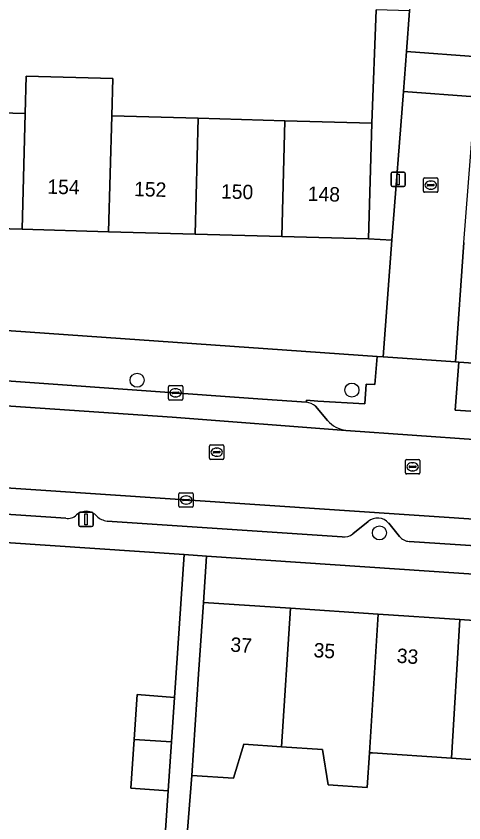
# Model space of a CAD drawing. Extents: x 159053 to 160042, y 380449 to 381423.
# Drawn here: x 159387.7 to 159418.7, y 381158.5 to 381214.5 of the extents above; entities that cross this region are included whole.
import ezdxf

# ---------------------------------------------------------------- set-up
doc = ezdxf.new("R2010")
doc.units = 0
for name, color, linetype in [('IMGEO_Berm_groen', 7, 'Continuous'), ('IMGEO_Boom', 7, 'Continuous'), ('IMGEO_Erf', 7, 'Continuous'), ('IMGEO_Kolk', 7, 'Continuous'), ('IMGEO_Lichtmast', 7, 'Continuous'), ('IMGEO_Pand', 7, 'Continuous'), ('IMGEO_Pand_nummerreeks', 7, 'Continuous'), ('IMGEO_Parkeervlak_open', 7, 'Continuous'), ('IMGEO_Rijbaan_lokaal_open', 7, 'Continuous'), ('IMGEO_Rioolput', 7, 'Continuous'), ('IMGEO_Voetpad_open', 7, 'Continuous')]:
    doc.layers.add(name, color=color, linetype=linetype)

msp = doc.modelspace()

# ---------------------------------------------------------------- linework, layer by layer
at = {"layer": 'IMGEO_Berm_groen'}
msp.add_lwpolyline([(159414.538, 381209.296), (159414.752, 381212.087), (159414.968, 381214.908), (159412.643, 381214.977), (159412.342, 381207.116), (159412.123, 381199.079), (159413.749, 381198.987)], close=True, dxfattribs=at)
at = {"layer": 'IMGEO_Boom'}
for centre in [(159396.061, 381189.257), (159410.962, 381188.573), (159412.878, 381178.655)]:
    msp.add_circle(centre, 0.489, dxfattribs=at)
at = {"layer": 'IMGEO_Erf'}
for points in [[(159352.243, 381208.754), (159358.251, 381208.591), (159364.259, 381208.427), (159370.267, 381208.263), (159376.275, 381208.099), (159382.281, 381207.936), (159388.289, 381207.772), (159388.359, 381210.379), (159394.368, 381210.218), (159394.298, 381207.608), (159400.305, 381207.444), (159406.313, 381207.28), (159412.342, 381207.116), (159412.643, 381214.977)], [(159337.817, 381196.156), (159412.725, 381190.897), (159413.137, 381190.868), (159413.749, 381198.987), (159412.123, 381199.079), (159406.098, 381199.243), (159400.09, 381199.407), (159394.083, 381199.571), (159388.074, 381199.735), (159382.067, 381199.899), (159376.06, 381200.063), (159370.052, 381200.227), (159364.044, 381200.391), (159358.036, 381200.555), (159352.028, 381200.719)], [(159418.746, 381198.827), (159418.155, 381190.521), (159418.399, 381190.504), (159489.16, 381185.654)], [(159465.572, 381146.862), (159463.56, 381159.946), (159457.638, 381160.343), (159451.96, 381160.723), (159446.274, 381161.104), (159440.588, 381161.485), (159434.913, 381161.865), (159429.234, 381162.245), (159423.569, 381162.624), (159417.883, 381163.005), (159412.393, 381163.373), (159412.184, 381163.387), (159412.031, 381160.979), (159409.33, 381161.165), (159408.933, 381163.61), (159406.07, 381163.806), (159403.458, 381163.985), (159402.742, 381161.616), (159399.854, 381161.814), (159399.452, 381156.561)]]:
    msp.add_lwpolyline(points, dxfattribs=at)
for points in [[(159395.856, 381164.312), (159396.06, 381167.421), (159398.657, 381167.233), (159399.325, 381177.147), (159374.158, 381178.842), (159370.465, 381164.045), (159365.639, 381161.495), (159363.677, 381133.592), (159398.457, 381131.162), (159398.959, 381143.89), (159397.15, 381152.623), (159396.964, 381150.031), (159393.385, 381150.287), (159393.57, 381152.879), (159388.745, 381153.224), (159388.848, 381154.667), (159395.186, 381154.243), (159395.426, 381157.83), (159398.017, 381157.657), (159398.223, 381160.746), (159395.633, 381160.919)], [(159400.883, 381177.042), (159400.666, 381173.825), (159406.716, 381173.419), (159412.792, 381173.011), (159418.457, 381172.631), (159424.13, 381172.25), (159429.823, 381171.867), (159435.525, 381171.485), (159441.199, 381171.104), (159446.901, 381170.721), (159452.564, 381170.341), (159458.247, 381169.959), (159464.177, 381169.561), (159464.393, 381172.763)]]:
    msp.add_lwpolyline(points, close=True, dxfattribs=at)
at = {"layer": 'IMGEO_Kolk'}
for p, q in [((159415.937, 381202.378), (159415.937, 381203.23)), ((159416.012, 381203.304), (159416.864, 381203.304)), ((159416.425, 381203.084), (159416.45, 381203.084)), ((159416.938, 381203.23), (159416.938, 381202.378)), ((159416.196, 381202.798), (159416.196, 381202.81)), ((159416.634, 381202.761), (159416.236, 381202.761)), ((159416.239, 381202.847), (159416.637, 381202.847)), ((159416.448, 381202.524), (159416.423, 381202.524)), ((159416.68, 381202.81), (159416.68, 381202.798)), ((159416.864, 381202.304), (159416.012, 381202.304)), ((159398.232, 381187.954), (159398.232, 381188.806)), ((159398.307, 381188.88), (159399.159, 381188.88)), ((159398.72, 381188.66), (159398.745, 381188.66)), ((159399.233, 381188.806), (159399.233, 381187.954)), ((159398.491, 381188.374), (159398.491, 381188.386)), ((159398.929, 381188.337), (159398.531, 381188.337)), ((159398.534, 381188.423), (159398.932, 381188.423)), ((159398.743, 381188.1), (159398.718, 381188.1)), ((159398.975, 381188.386), (159398.975, 381188.374)), ((159399.159, 381187.88), (159398.307, 381187.88)), ((159398.958, 381180.513), (159398.958, 381181.365)), ((159399.033, 381181.439), (159399.885, 381181.439)), ((159399.446, 381181.219), (159399.471, 381181.219)), ((159399.959, 381181.365), (159399.959, 381180.513)), ((159399.217, 381180.933), (159399.217, 381180.945)), ((159399.655, 381180.896), (159399.257, 381180.896)), ((159399.26, 381180.982), (159399.658, 381180.982)), ((159399.469, 381180.659), (159399.444, 381180.659)), ((159399.701, 381180.945), (159399.701, 381180.933)), ((159399.885, 381180.439), (159399.033, 381180.439))]:
    msp.add_line(p, q, dxfattribs=at)
for points in [[(159415.937, 381202.378), (159415.937, 381203.23)], [(159416.012, 381203.304), (159416.864, 381203.304)], [(159416.938, 381203.23), (159416.938, 381202.378)], [(159416.864, 381202.304), (159416.012, 381202.304)], [(159398.232, 381187.954), (159398.232, 381188.806)], [(159398.307, 381188.88), (159399.159, 381188.88)], [(159399.233, 381188.806), (159399.233, 381187.954)], [(159399.159, 381187.88), (159398.307, 381187.88)], [(159398.958, 381180.513), (159398.958, 381181.365)], [(159399.033, 381181.439), (159399.885, 381181.439)], [(159399.959, 381181.365), (159399.959, 381180.513)], [(159399.885, 381180.439), (159399.033, 381180.439)]]:
    msp.add_lwpolyline(points, dxfattribs=at)
for centre, radius, start, end in [((159416.014, 381203.228), 0.0765, 91.552, 178.448), ((159416.014, 381203.228), 0.0765, 91.552, 178.448), ((159416.862, 381203.228), 0.0765, 1.552, 88.448), ((159416.862, 381203.228), 0.0765, 1.552, 88.448), ((159416.236, 381202.807), 0.0403, 85.8775, 175.7526), ((159416.233, 381202.797), 0.0366, 178.938, 274.7102), ((159416.637, 381202.804), 0.043, 264.8664, 352.4533), ((159416.641, 381202.809), 0.0386, 1.7309, 96.639), ((159416.014, 381202.38), 0.0765, 181.552, 268.448), ((159416.014, 381202.38), 0.0765, 181.552, 268.448), ((159416.862, 381202.38), 0.0765, 271.552, 358.448), ((159416.862, 381202.38), 0.0765, 271.552, 358.448), ((159398.309, 381188.804), 0.0765, 91.552, 178.448), ((159398.309, 381188.804), 0.0765, 91.552, 178.448), ((159399.157, 381188.804), 0.0765, 1.552, 88.448), ((159399.157, 381188.804), 0.0765, 1.552, 88.448), ((159398.309, 381187.956), 0.0765, 181.552, 268.448), ((159398.309, 381187.956), 0.0765, 181.552, 268.448), ((159398.531, 381188.383), 0.0403, 85.8775, 175.7526), ((159398.528, 381188.373), 0.0366, 178.938, 274.7102), ((159398.932, 381188.38), 0.043, 264.8664, 352.4533), ((159398.936, 381188.385), 0.0386, 1.7309, 96.639), ((159399.157, 381187.956), 0.0765, 271.552, 358.448), ((159399.157, 381187.956), 0.0765, 271.552, 358.448), ((159399.035, 381181.363), 0.0765, 91.552, 178.448), ((159399.035, 381181.363), 0.0765, 91.552, 178.448), ((159399.883, 381181.363), 0.0765, 1.552, 88.448), ((159399.883, 381181.363), 0.0765, 1.552, 88.448), ((159399.257, 381180.942), 0.0403, 85.8775, 175.7526), ((159399.254, 381180.932), 0.0366, 178.938, 274.7102), ((159399.658, 381180.939), 0.043, 264.8664, 352.4533), ((159399.662, 381180.944), 0.0386, 1.7309, 96.639), ((159399.035, 381180.515), 0.0765, 181.552, 268.448), ((159399.035, 381180.515), 0.0765, 181.552, 268.448), ((159399.883, 381180.515), 0.0765, 271.552, 358.448), ((159399.883, 381180.515), 0.0765, 271.552, 358.448)]:
    msp.add_arc(centre, radius, start, end, dxfattribs=at)
for centre, major_axis, ratio, start_param, end_param in [((159416.424, 381202.804), (-0.387, 0.002), 0.722429, 4.712389, 7.853982), ((159416.449, 381202.804), (-0.39, 0.002), 0.717154, 1.570796, 4.712389), ((159398.719, 381188.38), (-0.387, 0.002), 0.722429, 4.712389, 7.853982), ((159398.744, 381188.38), (-0.39, 0.002), 0.717154, 1.570796, 4.712389), ((159399.445, 381180.939), (-0.387, 0.002), 0.722429, 4.712389, 7.853982), ((159399.47, 381180.939), (-0.39, 0.002), 0.717154, 1.570796, 4.712389)]:
    msp.add_ellipse(centre, major_axis=major_axis, ratio=ratio, start_param=start_param, end_param=end_param, dxfattribs=at)
at = {"layer": 'IMGEO_Lichtmast'}
for p, q in [((159413.681, 381202.8), (159413.681, 381203.6)), ((159413.681, 381203.6), (159413.681, 381202.8)), ((159413.781, 381203.7), (159414.571, 381203.7)), ((159414.571, 381203.7), (159413.781, 381203.7)), ((159414.671, 381203.6), (159414.671, 381202.8)), ((159414.671, 381202.8), (159414.671, 381203.6)), ((159414.571, 381202.7), (159413.781, 381202.7)), ((159413.781, 381202.7), (159414.571, 381202.7)), ((159392.114, 381180.095), (159392.904, 381180.095)), ((159392.904, 381180.095), (159392.114, 381180.095)), ((159392.014, 381179.195), (159392.014, 381179.995)), ((159392.014, 381179.995), (159392.014, 381179.195)), ((159393.004, 381179.995), (159393.004, 381179.195)), ((159393.004, 381179.195), (159393.004, 381179.995)), ((159392.904, 381179.095), (159392.114, 381179.095)), ((159392.114, 381179.095), (159392.904, 381179.095))]:
    msp.add_line(p, q, dxfattribs=at)
for points in [[(159414.101, 381203.575), (159414.251, 381203.575), (159414.251, 381202.825), (159414.101, 381202.825), (159414.101, 381203.575)], [(159392.434, 381179.97), (159392.584, 381179.97), (159392.584, 381179.22), (159392.434, 381179.22), (159392.434, 381179.97)]]:
    msp.add_lwpolyline(points, dxfattribs=at)
for centre, start, end in [((159413.781, 381203.6), 90, 180), ((159413.781, 381203.6), 90, 180), ((159414.571, 381203.6), 0, 90), ((159414.571, 381203.6), 360, 90), ((159413.781, 381202.8), 180, 270), ((159413.781, 381202.8), 180, 270), ((159414.571, 381202.8), 270, 0), ((159414.571, 381202.8), 270, 0), ((159392.114, 381179.995), 90, 180), ((159392.114, 381179.995), 90, 180), ((159392.904, 381179.995), 0, 90), ((159392.904, 381179.995), 360, 90), ((159392.114, 381179.195), 180, 270), ((159392.114, 381179.195), 180, 270), ((159392.904, 381179.195), 270, 0), ((159392.904, 381179.195), 270, 0)]:
    msp.add_arc(centre, 0.1, start, end, dxfattribs=at)
at = {"layer": 'IMGEO_Pand'}
for points in [[(159394.298, 381207.608), (159394.368, 381210.218), (159388.359, 381210.379), (159388.289, 381207.772), (159388.074, 381199.735), (159394.083, 381199.571)], [(159388.289, 381207.772), (159382.281, 381207.936), (159382.067, 381199.899), (159388.074, 381199.735)], [(159400.305, 381207.444), (159394.298, 381207.608), (159394.083, 381199.571), (159400.09, 381199.407)], [(159400.305, 381207.444), (159400.09, 381199.407), (159406.098, 381199.243), (159406.313, 381207.28)], [(159406.098, 381199.243), (159412.123, 381199.079), (159412.342, 381207.116), (159406.313, 381207.28)], [(159406.716, 381173.419), (159400.666, 381173.825), (159400.329, 381168.837), (159399.854, 381161.814), (159402.742, 381161.616), (159403.458, 381163.985), (159406.07, 381163.806)], [(159412.792, 381173.011), (159406.716, 381173.419), (159406.07, 381163.806), (159408.933, 381163.61), (159409.33, 381161.165), (159412.031, 381160.979), (159412.184, 381163.387)], [(159418.457, 381172.631), (159412.792, 381173.011), (159412.184, 381163.387), (159412.393, 381163.373), (159417.883, 381163.005)], [(159423.569, 381162.624), (159424.13, 381172.25), (159418.457, 381172.631), (159417.883, 381163.005)], [(159398.45, 381164.138), (159398.657, 381167.233), (159396.06, 381167.421), (159395.856, 381164.312)], [(159398.45, 381164.138), (159395.856, 381164.312), (159395.633, 381160.919), (159398.223, 381160.746)]]:
    msp.add_lwpolyline(points, close=True, dxfattribs=at)
at = {"layer": 'IMGEO_Parkeervlak_open'}
for points in [[(159407.806, 381187.721), (159404.772, 381187.938), (159372.118, 381190.286), (159359.449, 381191.183), (159340.776, 381192.489), (159338.035, 381192.671), (159337.916, 381190.875), (159340.654, 381190.693), (159359.323, 381189.387), (159371.994, 381188.49), (159398.502, 381186.692), (159410.545, 381185.773)], [(159409.278, 381186.45), (159408.429, 381187.442)], [(159487.911, 381173.518), (159488.858, 381174.48), (159489.604, 381174.872), (159487.158, 381175.068), (159371.374, 381182.825)], [(159374.453, 381180.793), (159391.104, 381179.669)], [(159393.972, 381179.475), (159410.298, 381178.378)], [(159411.034, 381178.577), (159412.087, 381179.444)], [(159413.518, 381179.331), (159414.264, 381178.408)], [(159414.944, 381178.056), (159425.958, 381177.33)]]:
    msp.add_lwpolyline(points, dxfattribs=at)
for centre, radius, start, end in [((159407.705, 381186.661), 1.065, 47.1753, 84.5758), ((159410.851, 381187.869), 2.118, 222.0608, 261.7051), ((159392.508, 381179.161), 0.992, 40.7678, 131.4312), ((159391.26, 381180.475), 0.821, 259.0341, 316.0317), ((159394.153, 381180.79), 1.327, 227.6484, 262.1507), ((159412.744, 381178.648), 1.032, 41.4311, 129.5388), ((159410.433, 381179.338), 0.969, 261.9728, 308.2869), ((159415.002, 381179), 0.946, 218.7542, 266.5093)]:
    msp.add_arc(centre, radius, start, end, dxfattribs=at)
at = {"layer": 'IMGEO_Rijbaan_lokaal_open'}
for points in [[(159418.719, 381267.127), (159418.471, 381262.899), (159418.138, 381256.93), (159417.564, 381250), (159416.846, 381241.338), (159416.645, 381238.911), (159416.349, 381234.665), (159414.999, 381215.304), (159414.968, 381214.908), (159414.752, 381212.087), (159419.735, 381211.721)], [(159482.078, 381180.662), (159455.525, 381182.85), (159444.275, 381183.548), (159419.745, 381185.125), (159410.545, 381185.773), (159398.502, 381186.692), (159371.994, 381188.49), (159359.323, 381189.387), (159340.654, 381190.693), (159337.916, 381190.875), (159332.905, 381191.207), (159309.922, 381192.73), (159287.147, 381194.26), (159278.1, 381194.857), (159274.38, 381195.177), (159273.367, 381195.267), (159264.523, 381195.918), (159264.142, 381189.576), (159270.165, 381189.159), (159290.318, 381187.762), (159293.502, 381187.602), (159310.558, 381186.943)], [(159311.37, 381186.961), (159314.829, 381186.674), (159327.267, 381185.896), (159339.334, 381185.09), (159355.92, 381183.977), (159359.695, 381183.717), (159368.882, 381183.022), (159371.374, 381182.825), (159487.158, 381175.068), (159489.604, 381174.872), (159490.216, 381174.956), (159490.385, 381174.858)]]:
    msp.add_lwpolyline(points, dxfattribs=at)
for points in [[(159419.735, 381211.721), (159414.752, 381212.087), (159414.538, 381209.296), (159419.521, 381208.929)], [(159418.746, 381198.827), (159419.521, 381208.929), (159414.538, 381209.296), (159413.749, 381198.987), (159413.137, 381190.868), (159418.155, 381190.521)]]:
    msp.add_lwpolyline(points, close=True, dxfattribs=at)
at = {"layer": 'IMGEO_Rioolput'}
for p, q in [((159401.083, 381183.833), (159401.083, 381184.685)), ((159401.158, 381184.759), (159402.01, 381184.759)), ((159401.571, 381184.539), (159401.596, 381184.539)), ((159402.084, 381184.685), (159402.084, 381183.833)), ((159401.342, 381184.253), (159401.342, 381184.265)), ((159401.78, 381184.216), (159401.382, 381184.216)), ((159401.385, 381184.302), (159401.783, 381184.302)), ((159401.594, 381183.979), (159401.569, 381183.979)), ((159401.826, 381184.265), (159401.826, 381184.253)), ((159402.01, 381183.759), (159401.158, 381183.759)), ((159414.679, 381182.817), (159414.679, 381183.669)), ((159414.754, 381183.743), (159415.606, 381183.743)), ((159415.167, 381183.523), (159415.192, 381183.523)), ((159415.68, 381183.669), (159415.68, 381182.817)), ((159414.938, 381183.237), (159414.938, 381183.249)), ((159415.376, 381183.2), (159414.978, 381183.2)), ((159414.981, 381183.286), (159415.379, 381183.286)), ((159415.19, 381182.963), (159415.165, 381182.963)), ((159415.422, 381183.249), (159415.422, 381183.237)), ((159415.606, 381182.743), (159414.754, 381182.743))]:
    msp.add_line(p, q, dxfattribs=at)
for points in [[(159401.083, 381183.833), (159401.083, 381184.685)], [(159401.158, 381184.759), (159402.01, 381184.759)], [(159402.084, 381184.685), (159402.084, 381183.833)], [(159402.01, 381183.759), (159401.158, 381183.759)], [(159414.679, 381182.817), (159414.679, 381183.669)], [(159414.754, 381183.743), (159415.606, 381183.743)], [(159415.68, 381183.669), (159415.68, 381182.817)], [(159415.606, 381182.743), (159414.754, 381182.743)]]:
    msp.add_lwpolyline(points, dxfattribs=at)
for centre, radius, start, end in [((159401.16, 381184.683), 0.0765, 91.552, 178.448), ((159401.16, 381184.683), 0.0765, 91.552, 178.448), ((159402.008, 381184.683), 0.0765, 1.552, 88.448), ((159402.008, 381184.683), 0.0765, 1.552, 88.448), ((159401.382, 381184.262), 0.0403, 85.8775, 175.7526), ((159401.379, 381184.252), 0.0366, 178.938, 274.7102), ((159401.783, 381184.259), 0.043, 264.8664, 352.4533), ((159401.787, 381184.264), 0.0386, 1.7309, 96.639), ((159401.16, 381183.835), 0.0765, 181.552, 268.448), ((159401.16, 381183.835), 0.0765, 181.552, 268.448), ((159402.008, 381183.835), 0.0765, 271.552, 358.448), ((159402.008, 381183.835), 0.0765, 271.552, 358.448), ((159414.756, 381183.667), 0.0765, 91.552, 178.448), ((159414.756, 381183.667), 0.0765, 91.552, 178.448), ((159415.604, 381183.667), 0.0765, 1.552, 88.448), ((159415.604, 381183.667), 0.0765, 1.552, 88.448), ((159414.978, 381183.246), 0.0403, 85.8775, 175.7526), ((159414.975, 381183.236), 0.0366, 178.938, 274.7102), ((159415.379, 381183.243), 0.043, 264.8664, 352.4533), ((159415.383, 381183.248), 0.0386, 1.7309, 96.639), ((159414.756, 381182.819), 0.0765, 181.552, 268.448), ((159414.756, 381182.819), 0.0765, 181.552, 268.448), ((159415.604, 381182.819), 0.0765, 271.552, 358.448), ((159415.604, 381182.819), 0.0765, 271.552, 358.448)]:
    msp.add_arc(centre, radius, start, end, dxfattribs=at)
for centre, major_axis, ratio, start_param, end_param in [((159401.57, 381184.259), (-0.387, 0.002), 0.722429, 4.712389, 7.853982), ((159401.595, 381184.259), (-0.39, 0.002), 0.717154, 1.570796, 4.712389), ((159415.166, 381183.243), (-0.387, 0.002), 0.722429, 4.712389, 7.853982), ((159415.191, 381183.243), (-0.39, 0.002), 0.717154, 1.570796, 4.712389)]:
    msp.add_ellipse(centre, major_axis=major_axis, ratio=ratio, start_param=start_param, end_param=end_param, dxfattribs=at)
at = {"layer": 'IMGEO_Voetpad_open'}
msp.add_lwpolyline([(159337.817, 381196.156), (159338.035, 381192.671), (159340.776, 381192.489), (159359.449, 381191.183), (159372.118, 381190.286), (159404.772, 381187.938), (159407.806, 381187.721), (159407.816, 381187.861), (159408.6, 381187.806), (159411.863, 381187.621), (159411.95, 381188.985), (159412.565, 381188.953), (159412.703, 381190.629), (159412.725, 381190.897)], close=True, dxfattribs=at)
for points in [[(159418.399, 381190.504), (159418.155, 381190.521), (159413.137, 381190.868), (159412.725, 381190.897), (159412.703, 381190.629), (159412.565, 381188.953), (159411.95, 381188.985), (159411.863, 381187.621), (159408.6, 381187.806), (159407.816, 381187.861), (159407.806, 381187.721)], [(159418.399, 381190.504), (159418.138, 381187.184), (159422.811, 381186.885), (159422.8, 381186.735), (159426.257, 381186.469), (159444.396, 381185.344), (159455.655, 381184.645), (159472.676, 381183.243), (159478.72, 381182.801), (159479.821, 381182.74)], [(159422.8, 381186.735), (159422.811, 381186.885), (159418.138, 381187.184), (159418.399, 381190.504)], [(159491.782, 381185.731), (159489.16, 381185.654), (159418.399, 381190.504)], [(159408.429, 381187.442), (159409.278, 381186.45)], [(159410.545, 381185.773), (159419.745, 381185.125)], [(159312.209, 381183.497), (159318.756, 381183.227), (159332.046, 381182.37), (159331.815, 381178.679), (159333.248, 381178.562), (159335.834, 381178.383), (159339.359, 381178.144), (159339.406, 381178.814), (159339.483, 381179.88), (159356.805, 381178.73), (159356.901, 381179.946), (159374.158, 381178.842), (159399.325, 381177.147), (159400.883, 381177.042), (159464.393, 381172.763), (159465.838, 381172.666), (159491.067, 381170.966), (159495.274, 381170.535)], [(159391.104, 381179.669), (159374.453, 381180.793)], [(159410.298, 381178.378), (159393.972, 381179.475)], [(159412.087, 381179.444), (159411.034, 381178.577)], [(159414.264, 381178.408), (159413.518, 381179.331)], [(159425.958, 381177.33), (159414.944, 381178.056)], [(159399.452, 381156.561), (159399.854, 381161.814), (159400.329, 381168.837), (159400.666, 381173.825), (159400.883, 381177.042), (159399.325, 381177.147), (159398.657, 381167.233), (159398.45, 381164.138), (159398.223, 381160.746), (159398.017, 381157.657)]]:
    msp.add_lwpolyline(points, dxfattribs=at)
for centre, radius, start, end in [((159407.705, 381186.661), 1.065, 47.1753, 84.5758), ((159410.851, 381187.869), 2.118, 222.0608, 261.7051), ((159392.508, 381179.161), 0.992, 40.7678, 131.4312), ((159391.26, 381180.475), 0.821, 259.0341, 316.0317), ((159394.153, 381180.79), 1.327, 227.6484, 262.1507), ((159412.744, 381178.648), 1.032, 41.4311, 129.5388), ((159410.433, 381179.338), 0.969, 261.9728, 308.2869), ((159415.002, 381179), 0.946, 218.7542, 266.5093)]:
    msp.add_arc(centre, radius, start, end, dxfattribs=at)

# ---------------------------------------------------------------- texts
at = {"layer": 'IMGEO_Pand_nummerreeks'}
for s, rotation, p in [('154', 358.4358, (159389.822, 381202.209)), ('152', 358.4381, (159395.843, 381202.044)), ('150', 358.4381, (159401.873, 381201.879)), ('148', 358.4381, (159407.896, 381201.715)), ('37', 356.159, (159402.509, 381170.414)), ('35', 356.1612, (159408.282, 381170.026)), ('33', 356.1612, (159414.056, 381169.638))]:
    msp.add_text(s, height=1, rotation=rotation, dxfattribs=at).set_placement(p)

doc.saveas('drawing.dxf')
